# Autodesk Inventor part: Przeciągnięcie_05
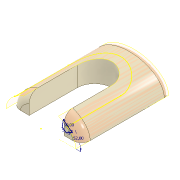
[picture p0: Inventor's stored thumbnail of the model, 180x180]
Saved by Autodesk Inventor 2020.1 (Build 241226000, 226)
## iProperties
Manager: www.cadconsulting.pl
Company: Fabian Stasiak CAD Consulting
Created: 2019-07
Part Number: Przeciągnięcie_05
Material: Ogólny
Document SubType Name: Modeling
Designer: F.Stasiak
Density: 1 g/cm^3
Appearance: Jasnobeżowa
Author: F.Stasiak
Subject: Zbiór ćwiczeń. Autodesk Inventor 2020. Kurs podstawowy
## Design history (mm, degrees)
sketch "Szkic1" dims "d0" = 40, "d1" = 26
  geometry: L1 (-40, 0)-(40, 0); 2 further points; 1 other entity
  constraints: 2 end point, 1 coincident, 1 horizontal, 1 midpoint, 4 other
extrude "Wyciągnięcie proste1" new body sketch "Szkic1" distance "d2" = 100; taper "d3" = 0 deg
sketch "Szkic2"
  geometry: L1 (0, 0)-(80, 0) reference; L2 (20, 0)-(20, -55); L3 (60, -55)-(60, 0); A1 r 20 centre (40, -55) between (20, -55) and (60, -55); 2 further points
  constraints: 4 end point, 2 point on circle, 2 point on line, 2 tangent, 1 centre point, 1 midpoint, 1 perpendicular, 1 vertical, 1 vertical alignment
  dimensions: "d4" = 20 radius of A1; "d5" = 55 distance from line of A1.centre L1
extrude "Wyciągnięcie proste2" cut sketch "Szkic2" extent not by distance; stored distance "d6" = 0; taper "d7" = 0 deg
node "Płaszczyzna konstrukcyjna1"
sketch "Szkic3"
  geometry: L1 (20, 0)-(20, -55) reference; L2 (-20, -55)-(-20, 0) reference; L3 (-30, 2.865)-(-30, -55); L4 (30, -55)-(30, 2.865); L5 (30, 2.865)-(30, 7.865); L6 (-30, 2.865)-(-30, 7.865); 1 further point
  constraints: 8 end point, 3 parallel, 2 horizontal alignment, 2 vertical, 2 other
  dimensions: "d9" = 5 distance of L4.end L5.end; "d10" = 60 distance from line of L6.end L5
feature "POW.PROWADZĄCA" dims "d11" = 0, "d12" = 0
feature "Wydłuż1" dims "d13" = 6.5
sketch "Szkic 3D1"
  node "Przecięcie 3D1"
node "Płaszczyzna konstrukcyjna2"
sketch "Szkic4"
  geometry: L1 (5.77, -3.239)-(-1.724, -6.267); L2 (-1.724, -6.267)-(-5.664, -3.189); L3 (-5.664, -3.189)-(-4.539, 4.815); L4 (-10, -17.197)-(10, -17.197) reference; L5 (-3.694, -4.728)-(0.616, 0.788); L6 (-4.539, 4.815)-(5.77, -3.239); 3 further points
  constraints: 10 end point, 2 midpoint, 1 coincident, 1 equal length, 1 parallel, 1 point on line
  dimensions: "d16" = 5 distance of L1.end L2.end; "d18" = 7 distance of L5.end L5.start; "d19" = 6 distance from line of point (0, 0) L2; "d20" = 60 deg angle of L1 L3; "d21" = 52 deg angle of L4 L5
fillet "Zaokrąglenie1" dims "d22" = 10
fillet "Zaokrąglenie2" dims "d23" = 5
node "Bryła1"
body "Srf1"
